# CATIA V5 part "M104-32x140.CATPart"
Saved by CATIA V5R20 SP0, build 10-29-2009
Part number: M104-32x140
Source: Unknown
Bounding box of the stored display mesh (mm): x -15.868 to 15.868, y -15.868 to 15.868, z 0 to 140
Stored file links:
  C:\Users\Utente\Desktop\IO LAVORO\3D X SITO CF\X SITO\M104\M104-32x140.CATPart

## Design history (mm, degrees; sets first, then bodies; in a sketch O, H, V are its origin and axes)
Body1 (main body)
  Solid1 "PartBody": solid without history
